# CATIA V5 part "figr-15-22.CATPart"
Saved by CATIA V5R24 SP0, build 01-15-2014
Part number: Part1
Bounding box of the stored display mesh (mm): x -75 to 76, y -66.397 to 33.603, z 0 to 100
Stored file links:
  D:\KAVITA\CATIA V5-6R2014 Project_ Kavita\CATIA V5-6R2014_partfiles\Partfiles\c15_catia_v5-6r2014_prt\figr-15-22.CATPart
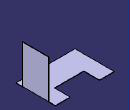
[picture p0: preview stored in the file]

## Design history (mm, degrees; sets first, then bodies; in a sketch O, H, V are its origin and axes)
SheetMetalParameters1: Thickness 1, BendRadius 1, KFactor 0.325257 {= log(min(100,max(20*SheetMetalParameters1.BendRadius,SheetMetalParameters1.Thickness)/SheetMetalParameters1.Thickness))/log(100)/2}, ReliefRadialLength 1, ReliefAxialLength 2, MinimumBendRadius 0
Body1 (main body)
  Sketch1 on xy-plane, origin (0, 0, 0), H (1, 0, 0), V (0, 1, 0)
    line L1 (-37.5, 33.6029) -> (-37.5, -6.3971)
    line L2 (-37.5, -6.3971) -> (37.5, -6.3971)
    line L3 (37.5, -6.3971) -> (37.5, 33.6029)
    line L4 (37.5, 33.6029) -> (75, 33.6029)
    line L5 (75, 33.6029) -> (75, -66.3971)
    line L6 (75, -66.3971) -> (-75, -66.3971)
    line L7 (-75, -66.3971) -> (-75, 33.6029)
    point P8 (-75, 33.6029)
    line L8 (-75, 33.6029) -> (-37.5, 33.6029)
    length L7 = 100
    length L1 = 40
    length L6 = 150
    distance L1 L3 = 75
    vertical: L1 V, L3 V, L5 V, L7 V
    horizontal: L2 H, L4 H, L6 H, L8 H
    coincidence: P8 L4
    symmetry: L7 L5 V, L1 L3 V
  Wall1: Thickness 1, Profile Sketch1
  d_NewWallOnEdge1: NewWallOnEdge_Edge edge [face of Wall1 | face of Wall1], NewWallOnEdge_Length 100, NewWallOnEdge_HeightLimitOffset 0, NewWallOnEdge_WidthOffset1 -16, NewWallOnEdge_WidthOffset2 -17, NewWallOnEdge_Angle 90, NewWallOnEdge_BendRadiusValue 1 {= SheetMetalParameters1.BendRadius}, NewWallOnEdge_BendTable SheetMetalParameters1, KFacteur 0.325257 {= log(min(100,max(20*d_NewWallOnEdge1.Radius,SheetMetalParameters1.Thickness)/SheetMetalParameters1.Thickness))/log(100)/2}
